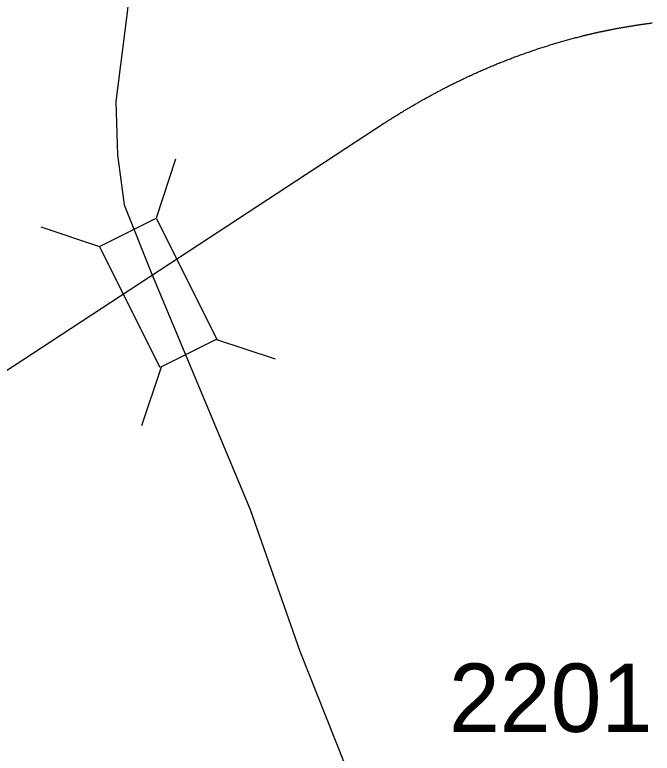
# Model space of a CAD drawing. Extents: x 1364363 to 1407445, y 538563 to 573342.
# Drawn here: x 1373779 to 1374945, y 560433 to 561783 of the extents above; entities that cross this region are included whole.
import ezdxf

# ---------------------------------------------------------------- set-up
doc = ezdxf.new("R2010")
doc.units = 0
for name, color, linetype in [('Exist Railroad Mainline', 7, 'Continuous'), ('Exist Road Secondary Structure Standard Bridge CELL', 7, 'Continuous'), ('Exist Road Secondary Type 51 Attributed', 7, 'Continuous'), ('Exist Road Secondary Type 51 Number Label', 7, 'Continuous')]:
    doc.layers.add(name, color=color, linetype=linetype)

msp = doc.modelspace()

# ---------------------------------------------------------------- linework, layer by layer
at = {"layer": 'Exist Railroad Mainline'}
for points in [[(1374875, 561757), (1374876.3, 561757.3), (1374877.5, 561757.5), (1374878.7, 561757.7), (1374880, 561757.9), (1374881.3, 561758.2), (1374882.5, 561758.4), (1374883.8, 561758.6), (1374885, 561758.9), (1374886.2, 561759), (1374887.5, 561759.3), (1374888.8, 561759.5), (1374890, 561759.8), (1374891.2, 561760), (1374892.5, 561760.2), (1374893.8, 561760.4), (1374895, 561760.6), (1374896.3, 561760.8), (1374897.5, 561761), (1374898.7, 561761.3), (1374900, 561761.5), (1374901.3, 561761.7), (1374902.5, 561761.9), (1374903.7, 561762.1), (1374905, 561762.3), (1374906.2, 561762.5), (1374907.5, 561762.7), (1374908.8, 561762.9), (1374910, 561763.1), (1374911.2, 561763.3), (1374912.5, 561763.5), (1374913.8, 561763.8), (1374915, 561763.9), (1374916.3, 561764.1), (1374917.5, 561764.3), (1374918.7, 561764.5), (1374920, 561764.7), (1374921.3, 561764.9), (1374922.5, 561765), (1374923.7, 561765.3), (1374925, 561765.5), (1374926.2, 561765.6), (1374927.5, 561765.8), (1374928.8, 561766), (1374930, 561766.1), (1374931.2, 561766.3), (1374932.5, 561766.5), (1374933.8, 561766.7), (1374935, 561766.9), (1374936.2, 561767), (1374937.5, 561767.2), (1374938.7, 561767.4), (1374940.1, 561767.6), (1374941.4, 561767.7), (1374942.6, 561767.9), (1374943.8, 561768.1), (1374945.2, 561768.2)], [(1374813.6, 561743.5), (1374814.2, 561743.6), (1374814.9, 561743.8), (1374815.5, 561743.9), (1374816.1, 561744.1), (1374816.7, 561744.2), (1374817.4, 561744.4), (1374818, 561744.5), (1374818.5, 561744.7), (1374819.2, 561744.9), (1374819.8, 561745), (1374820.4, 561745.2), (1374821, 561745.3), (1374821.6, 561745.5), (1374822.2, 561745.6), (1374822.9, 561745.8), (1374823.5, 561745.9), (1374824.1, 561746.1), (1374824.8, 561746.2), (1374825.4, 561746.4), (1374826, 561746.5), (1374826.6, 561746.6), (1374827.3, 561746.8), (1374827.9, 561746.9), (1374828.4, 561747.1), (1374829, 561747.2), (1374829.6, 561747.4), (1374830.2, 561747.5), (1374830.9, 561747.6), (1374831.5, 561747.8), (1374832.1, 561747.9), (1374832.8, 561748.1), (1374833.4, 561748.2), (1374834, 561748.4), (1374834.6, 561748.5), (1374835.3, 561748.6), (1374835.9, 561748.8), (1374836.5, 561748.9), (1374837.1, 561749.1), (1374837.7, 561749.2), (1374838.3, 561749.4), (1374838.9, 561749.5), (1374839.7, 561749.6), (1374840.3, 561749.8), (1374840.8, 561749.9), (1374841.4, 561750.1), (1374842, 561750.2), (1374842.6, 561750.3), (1374843.3, 561750.4), (1374843.9, 561750.5), (1374844.5, 561750.7), (1374845.1, 561750.9), (1374845.7, 561751), (1374846.3, 561751.1), (1374847, 561751.3), (1374847.7, 561751.4), (1374848.3, 561751.6), (1374848.9, 561751.7), (1374849.5, 561751.8), (1374850.1, 561751.9), (1374850.7, 561752.1), (1374851.4, 561752.2), (1374852, 561752.3), (1374852.6, 561752.4), (1374853.2, 561752.6), (1374853.9, 561752.7), (1374854.5, 561752.9), (1374855.1, 561753), (1374855.8, 561753.1), (1374856.4, 561753.3), (1374857, 561753.4), (1374857.6, 561753.5), (1374858.2, 561753.6), (1374858.8, 561753.8), (1374859.4, 561753.9), (1374860, 561754), (1374860.6, 561754.1), (1374861.3, 561754.2), (1374861.9, 561754.4), (1374862.5, 561754.5), (1374863.1, 561754.7), (1374863.8, 561754.8), (1374864.4, 561754.9), (1374865, 561755), (1374865.6, 561755.2), (1374866.2, 561755.3), (1374866.8, 561755.5), (1374867.5, 561755.5), (1374868.2, 561755.6), (1374868.8, 561755.8), (1374869.4, 561755.9), (1374870, 561756), (1374870.6, 561756.1), (1374871.2, 561756.2), (1374871.9, 561756.4), (1374872.5, 561756.5), (1374873.1, 561756.6), (1374873.7, 561756.7), (1374874.4, 561756.9), (1374875, 561757)], [(1374608.5, 561670.1), (1374610.5, 561671.1), (1374612.5, 561672), (1374614.5, 561672.9), (1374616.5, 561673.8), (1374618.5, 561674.8), (1374620.5, 561675.6), (1374622.5, 561676.6), (1374624.5, 561677.4), (1374626.5, 561678.4), (1374628.5, 561679.2), (1374630.5, 561680.1), (1374632.5, 561681), (1374634.6, 561681.9), (1374636.7, 561682.8), (1374638.6, 561683.7), (1374640.7, 561684.5), (1374642.6, 561685.4), (1374644.8, 561686.3), (1374646.7, 561687.1), (1374648.8, 561688), (1374650.7, 561688.8), (1374652.9, 561689.7), (1374654.9, 561690.5), (1374656.9, 561691.4), (1374658.9, 561692.2), (1374661, 561693.1), (1374663, 561693.9), (1374665, 561694.7), (1374667.1, 561695.5), (1374669.2, 561696.3), (1374671.2, 561697.1), (1374673.3, 561697.9), (1374675.2, 561698.8), (1374677.4, 561699.6), (1374679.4, 561700.4), (1374681.5, 561701.2), (1374683.5, 561701.9), (1374685.7, 561702.8), (1374687.6, 561703.5), (1374689.8, 561704.3), (1374691.7, 561705.1), (1374693.9, 561705.9), (1374695.9, 561706.6), (1374698, 561707.4), (1374700, 561708.1), (1374702.1, 561709), (1374704.1, 561709.7), (1374706.3, 561710.4), (1374708.3, 561711.2), (1374710.4, 561711.9), (1374712.5, 561712.6), (1374714.5, 561713.4), (1374716.6, 561714.1), (1374718.8, 561714.8), (1374720.7, 561715.6), (1374722.9, 561716.2), (1374725, 561717), (1374727, 561717.7), (1374729.1, 561718.4), (1374731.3, 561719.1), (1374733.2, 561719.8), (1374735.4, 561720.5), (1374737.4, 561721.2), (1374739.6, 561721.9), (1374741.7, 561722.5), (1374743.7, 561723.3), (1374745.9, 561723.9), (1374748, 561724.7), (1374750.2, 561725.3), (1374752.1, 561725.9), (1374754.3, 561726.5), (1374756.4, 561727.3), (1374758.5, 561727.9), (1374760.6, 561728.5), (1374762.8, 561729.2), (1374764.7, 561729.8), (1374766.9, 561730.5), (1374769, 561731.1), (1374771.1, 561731.8), (1374773.2, 561732.4), (1374775.4, 561733), (1374777.5, 561733.6), (1374779.6, 561734.2), (1374781.7, 561734.8), (1374783.9, 561735.4), (1374786, 561736), (1374788.1, 561736.6), (1374790.2, 561737.3), (1374792.4, 561737.8), (1374794.5, 561738.4), (1374796.6, 561739), (1374798.8, 561739.6), (1374800.9, 561740.1), (1374803, 561740.7), (1374805.1, 561741.3), (1374807.3, 561741.8), (1374809.4, 561742.4), (1374811.5, 561743), (1374813.6, 561743.5)], [(1374455.6, 561585.3), (1374457.1, 561586.2), (1374458.6, 561587.2), (1374460, 561588.2), (1374461.4, 561589.1), (1374463, 561590.1), (1374464.5, 561591), (1374466, 561591.9), (1374467.5, 561593), (1374469, 561593.9), (1374470.5, 561594.8), (1374472, 561595.8), (1374473.5, 561596.7), (1374475, 561597.6), (1374476.5, 561598.5), (1374478, 561599.4), (1374479.5, 561600.4), (1374481, 561601.3), (1374482.5, 561602.2), (1374484, 561603.2), (1374485.5, 561604.1), (1374487, 561605), (1374488.6, 561605.9), (1374490.2, 561606.8), (1374491.6, 561607.8), (1374493.1, 561608.6), (1374494.7, 561609.6), (1374496.1, 561610.4), (1374497.6, 561611.4), (1374499.1, 561612.2), (1374500.7, 561613.2), (1374502.3, 561614.1), (1374503.8, 561614.9), (1374505.2, 561615.8), (1374506.8, 561616.7), (1374508.4, 561617.6), (1374509.8, 561618.5), (1374511.4, 561619.4), (1374512.9, 561620.2), (1374514.5, 561621.1), (1374516, 561622.1), (1374517.5, 561622.9), (1374519, 561623.8), (1374520.6, 561624.6), (1374522.1, 561625.5), (1374523.6, 561626.4), (1374525.2, 561627.3), (1374526.8, 561628.1), (1374528.3, 561629), (1374529.8, 561629.9), (1374531.4, 561630.7), (1374532.9, 561631.6), (1374534.5, 561632.4), (1374536, 561633.2), (1374537.6, 561634.1), (1374539.2, 561634.9), (1374540.6, 561635.8), (1374542.2, 561636.6), (1374543.8, 561637.5), (1374545.4, 561638.3), (1374546.9, 561639.2), (1374548.5, 561640), (1374550, 561640.8), (1374551.7, 561641.7), (1374553.1, 561642.5), (1374554.7, 561643.3), (1374556.3, 561644.1), (1374557.9, 561644.9), (1374559.4, 561645.8), (1374561, 561646.6), (1374562.5, 561647.4), (1374564.1, 561648.3), (1374565.6, 561649.1), (1374567.3, 561649.9), (1374568.8, 561650.6), (1374570.3, 561651.4), (1374572, 561652.3), (1374573.5, 561653.1), (1374575.2, 561653.9), (1374576.6, 561654.7), (1374578.2, 561655.4), (1374579.9, 561656.3), (1374581.4, 561657.1), (1374583, 561657.8), (1374584.6, 561658.6), (1374586.1, 561659.4), (1374587.8, 561660.2), (1374589.4, 561660.9), (1374590.8, 561661.7), (1374592.5, 561662.5), (1374594.1, 561663.2), (1374595.8, 561664.1), (1374597.3, 561664.8), (1374598.8, 561665.5), (1374600.5, 561666.4), (1374602, 561667.1), (1374603.7, 561667.9), (1374605.3, 561668.6), (1374606.8, 561669.4), (1374608.5, 561670.1)], [(1373292.9, 560824.9), (1373489.7, 560953), (1374455.6, 561585.3)]]:
    msp.add_lwpolyline(points, dxfattribs=at)
at = {"layer": 'Exist Road Secondary Structure Standard Bridge CELL'}
for p, q in [((1374073.5, 561518.9), (1374037.8, 561411.5)), ((1373826.9, 561395.4), (1373934.3, 561359.7)), ((1374148.4, 561189.7), (1374255.8, 561154)), ((1374047.2, 561139), (1374011.5, 561031.6))]:
    msp.add_line(p, q, dxfattribs=at)
msp.add_lwpolyline([(1374037.8, 561411.5), (1374148.8, 561189.9), (1374045.3, 561138), (1373934.3, 561359.7)], close=True, dxfattribs=at)
at = {"layer": 'Exist Road Secondary Type 51 Attributed'}
for points in [[(1373942.7, 562378.3), (1373999.1, 562170), (1374009.9, 562038.4), (1373997.8, 561947.1), (1373985.6, 561791.8), (1373964.3, 561624.3), (1373967.3, 561526.9), (1373979.5, 561435.5), (1374029, 561311.7)], [(1374029, 561311.7), (1374210, 560878.4), (1374300.9, 560619.9), (1374382, 560415.3), (1374408, 560298.5), (1374407.3, 560223.6), (1374378.3, 560136.6), (1374345.2, 560066.2), (1374076.3, 559780.6), (1373765.5, 559467.2), (1373393.2, 559110.3)]]:
    msp.add_lwpolyline(points, dxfattribs=at)

# ---------------------------------------------------------------- texts
at = {"layer": 'Exist Road Secondary Type 51 Number Label'}
msp.add_text('2201', height=125, dxfattribs=at).set_placement((1374573.4, 560472))

doc.saveas('drawing.dxf')
